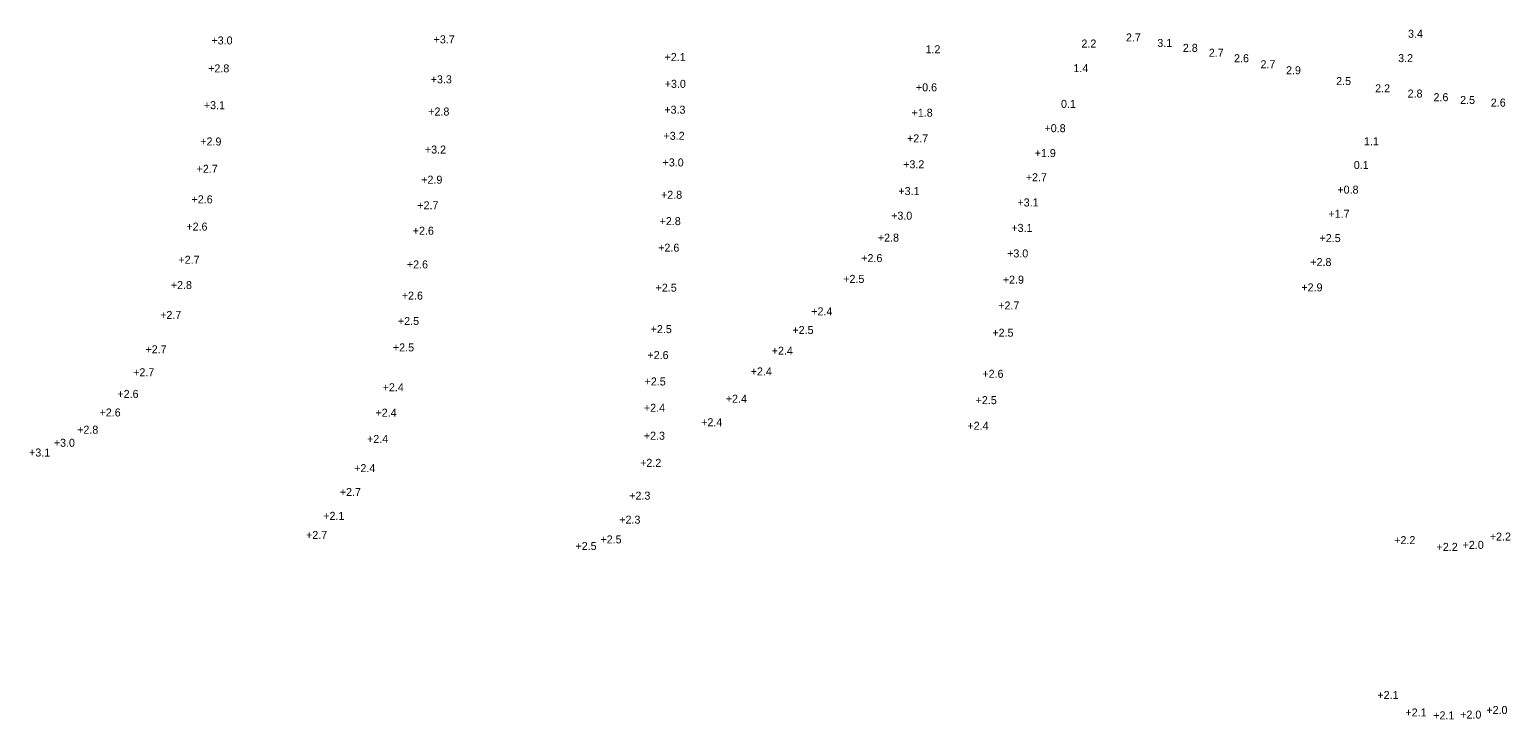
# Model space of a CAD drawing. Extents: x 837127 to 848654, y 3074248 to 3079868.
# Drawn here: x 844572 to 845150, y 3078820 to 3079089 of the extents above; entities that cross this region are included whole.
import ezdxf

# ---------------------------------------------------------------- set-up
doc = ezdxf.new("R2010")
doc.units = 0
doc.layers.add('V-HYDS-SOUN', color=7, linetype='Continuous')

msp = doc.modelspace()

# ---------------------------------------------------------------- texts
at = {"layer": 'V-HYDS-SOUN'}
for s, p in [('+3.0 ', (844642.89, 3079083.22)), ('+3.7 ', (844729.63, 3079083.64)), ('2.7', (844999.98, 3079084.39)), ('3.4', (845110.13, 3079085.83)), ('1.2', (844921.73, 3079079.78)), ('2.2', (844982.61, 3079082.01)), ('3.1', (845012.23, 3079082.24)), ('2.8', (845022.2, 3079080.32)), ('2.7', (845032.34, 3079078.41)), ('+2.8 ', (844641.61, 3079072.31)), ('+2.1 ', (844819.82, 3079076.74)), ('1.4', (844979.46, 3079072.4)), ('2.6', (845042.21, 3079076.27)), ('2.7', (845052.53, 3079073.92)), ('2.9', (845062.49, 3079071.58)), ('3.2', (845106.27, 3079076.32)), ('+3.3 ', (844728.5, 3079068.03)), ('+3.0 ', (844819.88, 3079066.28)), ('2.5', (845082.07, 3079067.36)), ('+0.6 ', (844917.97, 3079064.92)), ('2.2', (845097.3, 3079064.52)), ('2.8', (845109.97, 3079062.48)), ('2.6', (845120.08, 3079061.07)), ('2.5', (845130.48, 3079059.98)), ('+3.1 ', (844639.92, 3079057.95)), ('+2.8 ', (844727.54, 3079055.47)), ('+3.3 ', (844819.73, 3079056.18)), ('+1.8 ', (844916.28, 3079055)), ('0.1', (844974.63, 3079058.46)), ('2.6', (845142.45, 3079058.96)), ('+0.8 ', (844968.17, 3079048.97)), ('+2.9 ', (844638.53, 3079043.78)), ('+3.2 ', (844819.4, 3079045.99)), ('+2.7 ', (844914.49, 3079044.98)), ('1.1', (845092.92, 3079043.84)), ('+3.2 ', (844726.25, 3079040.63)), ('+1.9 ', (844964.34, 3079039.25)), ('+2.7 ', (844637.1, 3079033.11)), ('+3.0 ', (844819.04, 3079035.6)), ('+3.2 ', (844912.99, 3079034.87)), ('0.1', (845088.94, 3079034.59)), ('+2.9 ', (844724.81, 3079028.85)), ('+2.7 ', (844960.87, 3079029.82)), ('+2.6 ', (844635.12, 3079021.18)), ('+2.8 ', (844818.43, 3079022.96)), ('+3.1 ', (844911.13, 3079024.42)), ('+3.1 ', (844957.61, 3079019.96)), ('+0.8 ', (845082.54, 3079024.98)), ('+2.7 ', (844723.27, 3079018.87)), ('+3.0 ', (844908.29, 3079014.81)), ('+1.7 ', (845079.05, 3079015.55)), ('+2.6 ', (844633.09, 3079010.55)), ('+2.6 ', (844721.49, 3079008.94)), ('+2.8 ', (844817.89, 3079012.69)), ('+3.1 ', (844955.23, 3079010.04)), ('+2.6 ', (844817.33, 3079002.32)), ('+2.8 ', (844903.11, 3079006.24)), ('+2.5 ', (845075.58, 3079006.06)), ('+2.7 ', (844630, 3078997.59)), ('+2.6 ', (844896.63, 3078998.26)), ('+3.0 ', (844953.58, 3079000.08)), ('+2.8 ', (845071.97, 3078996.71)), ('+2.6 ', (844719.2, 3078995.78)), ('+2.8 ', (844627.03, 3078987.73)), ('+2.5 ', (844816.33, 3078986.71)), ('+2.5 ', (844889.6, 3078990.14)), ('+2.9 ', (844951.9, 3078989.83)), ('+2.9 ', (845068.48, 3078986.82)), ('+2.6 ', (844717.23, 3078983.61)), ('+2.7 ', (844950.11, 3078979.76)), ('+2.7 ', (844622.86, 3078976.07)), ('+2.5 ', (844715.71, 3078973.7)), ('+2.4 ', (844877.1, 3078977.46)), ('+2.5 ', (844814.39, 3078970.54)), ('+2.5 ', (844869.74, 3078970.2)), ('+2.5 ', (844947.81, 3078969.14)), ('+2.7 ', (844617.12, 3078962.65)), ('+2.5 ', (844713.76, 3078963.39)), ('+2.4 ', (844861.66, 3078962.11)), ('+2.6 ', (844813.13, 3078960.4)), ('+2.7 ', (844612.32, 3078953.7)), ('+2.5 ', (844812.02, 3078950.1)), ('+2.4 ', (844853.45, 3078954.01)), ('+2.6 ', (844943.93, 3078953.08)), ('+2.6 ', (844606.17, 3078945.24)), ('+2.4 ', (844709.74, 3078947.83)), ('+2.4 ', (844811.77, 3078939.82)), ('+2.4 ', (844843.74, 3078943.36)), ('+2.5 ', (844941.29, 3078942.81)), ('+2.6 ', (844599.19, 3078937.99)), ('+2.4 ', (844706.93, 3078937.9)), ('+2.4 ', (844834.13, 3078934.2)), ('+2.4 ', (844938.07, 3078932.79)), ('+2.8 ', (844590.45, 3078931.27)), ('+2.4 ', (844703.64, 3078927.67)), ('+2.3 ', (844811.73, 3078928.91)), ('+3.1 ', (844571.68, 3078922.37)), ('+3.0 ', (844581.33, 3078926.17)), ('+2.4 ', (844698.61, 3078916.26)), ('+2.2 ', (844810.28, 3078918.33)), ('+2.7 ', (844693.03, 3078906.95)), ('+2.3 ', (844806.02, 3078905.52)), ('+2.1 ', (844686.55, 3078897.64)), ('+2.3 ', (844802.14, 3078896.17)), ('+2.7 ', (844679.84, 3078890.19)), ('+2.5 ', (844794.79, 3078888.44)), ('+2.2 ', (845104.73, 3078888.16)), ('+2.2 ', (845142.06, 3078889.55)), ('+2.5 ', (844785.04, 3078885.88)), ('+2.2 ', (845121.29, 3078885.53)), ('+2.0 ', (845131.44, 3078886.32)), ('+2.1 ', (845098.15, 3078827.7)), ('+2.1 ', (845109.1, 3078820.9)), ('+2.1 ', (845119.99, 3078819.76)), ('+2.0 ', (845130.51, 3078820.07)), ('+2.0 ', (845140.71, 3078821.86))]:
    msp.add_text(s, height=3.125, dxfattribs=at).set_placement(p)

doc.saveas('drawing.dxf')
